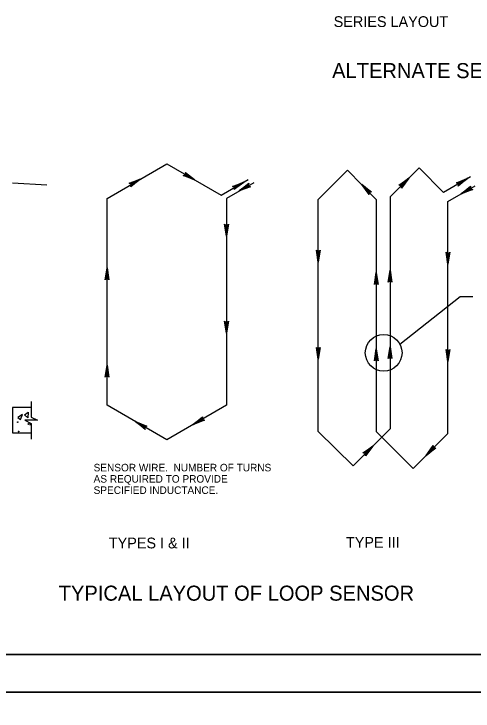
# Model space of a CAD drawing. Extents: x 2709 to 3899, y 22 to 1210.
# Drawn here: x 3073.4 to 3256.6, y 608.7 to 886.6 of the extents above; entities that cross this region are included whole.
import ezdxf

# ---------------------------------------------------------------- set-up
doc = ezdxf.new("R2010")
doc.units = 0
for name, color, linetype in [('1', 7, 'Continuous'), ('17', 7, 'Continuous'), ('2', 7, 'Continuous'), ('PLT-BNDY', 7, 'Continuous')]:
    doc.layers.add(name, color=color, linetype=linetype)

msp = doc.modelspace()

# ---------------------------------------------------------------- linework, layer by layer
at = {"layer": '1'}
for p, q in [((3534.86, 631.17), (2748.86, 631.17)), ((2748.86, 631.17), (3334.86, 631.17))]:
    msp.add_line(p, q, dxfattribs=at)
at = {"layer": '2'}
msp.add_line((3072.77, 819.25), (3086.52, 818.5), dxfattribs=at)
for points in [[(3158.17, 813.05), (3158.17, 730.55), (3134.42, 716.8), (3110.55, 730.55), (3110.55, 813.05), (3134.42, 826.8), (3156.05, 814.3)], [(3141.8, 823.17), (3141.8, 822.8), (3145.42, 820.42), (3141.8, 823.17), (3141.67, 823.42), (3145.42, 820.42), (3141.55, 822.42), (3141.3, 822.17), (3145.42, 820.42), (3140.92, 822.17), (3141.3, 822.17)], [(3255.55, 821.67), (3244.8, 815.42), (3235.05, 825.17), (3223.42, 813.67), (3223.42, 721.17), (3208.67, 706.42), (3194.8, 720.17), (3194.8, 812.67), (3206.42, 824.3), (3217.92, 812.67), (3217.92, 720.17), (3232.67, 705.42), (3246.55, 719.3), (3246.55, 811.8), (3257.42, 818.05)], [(3119.67, 818.92), (3119.92, 818.8), (3123.8, 820.67), (3119.67, 818.92), (3119.3, 819.05), (3123.8, 820.67), (3120.17, 818.3), (3120.17, 818.05), (3123.8, 820.67), (3120.05, 817.67), (3120.17, 818.05)], [(3156.05, 814.3), (3166.8, 820.55)], [(3227.3, 818.3), (3227.55, 818.17), (3230.92, 821.05), (3227.3, 818.3), (3226.92, 818.3), (3230.92, 821.05), (3227.92, 817.8), (3228.05, 817.55), (3230.92, 821.05), (3228.05, 817.17), (3228.05, 817.55)], [(3250.17, 819.17), (3250.55, 819.05), (3254.42, 821.05), (3250.17, 819.17), (3249.92, 819.3), (3254.42, 821.05), (3250.8, 818.67), (3250.8, 818.3), (3254.42, 821.05), (3250.67, 817.92), (3250.8, 818.3)], [(3169.05, 819.3), (3158.17, 813.05)], [(3160.92, 817.8), (3161.17, 817.55), (3165.05, 819.55), (3160.92, 817.8), (3160.55, 817.8), (3165.05, 819.55), (3161.42, 817.17), (3161.42, 816.8), (3165.05, 819.55), (3161.3, 816.55), (3161.42, 816.8)], [(3167.42, 817.8), (3167.17, 817.92), (3163.3, 816.05), (3167.42, 817.8), (3167.8, 817.67), (3163.3, 816.05), (3166.92, 818.42), (3166.92, 818.67), (3163.3, 816.05), (3167.05, 819.05), (3166.92, 818.67)], [(3214.92, 814.92), (3215.05, 815.17), (3212.17, 818.55), (3214.92, 814.92), (3215.05, 814.55), (3212.17, 818.55), (3215.42, 815.55), (3215.8, 815.67), (3212.17, 818.55), (3216.05, 815.67), (3215.8, 815.67)], [(3256.05, 816.55), (3255.8, 816.8), (3251.8, 814.8), (3256.05, 816.55), (3256.42, 816.55), (3251.8, 814.8), (3255.55, 817.17), (3255.55, 817.55), (3251.8, 814.8), (3255.55, 817.92), (3255.55, 817.55)], [(3158.8, 802.55), (3158.42, 802.42), (3158.17, 798.05), (3158.8, 802.55), (3158.92, 802.8), (3158.17, 798.05), (3157.92, 802.42), (3157.67, 802.55), (3158.17, 798.05), (3157.42, 802.8), (3157.67, 802.55)], [(3195.42, 792.17), (3195.05, 792.05), (3194.8, 787.67), (3195.42, 792.17), (3195.55, 792.42), (3194.8, 787.67), (3194.55, 792.05), (3194.3, 792.17), (3194.8, 787.67), (3194.05, 792.42), (3194.3, 792.17)], [(3247.17, 791.3), (3246.8, 791.05), (3246.55, 786.8), (3247.17, 791.3), (3247.3, 791.55), (3246.55, 786.8), (3246.3, 791.05), (3246.05, 791.3), (3246.55, 786.8), (3245.8, 791.55), (3246.05, 791.3)], [(3109.92, 780.8), (3110.3, 780.92), (3110.55, 785.3), (3109.92, 780.8), (3109.8, 780.55), (3110.55, 785.3), (3110.8, 780.92), (3111.05, 780.8), (3110.55, 785.3), (3111.3, 780.55), (3111.05, 780.8)], [(3222.92, 779.92), (3223.17, 780.05), (3223.42, 784.42), (3222.92, 779.92), (3222.67, 779.67), (3223.42, 784.42), (3223.67, 780.05), (3224.05, 779.92), (3223.42, 784.42), (3224.17, 779.67), (3224.05, 779.92)], [(3217.3, 778.92), (3217.67, 779.17), (3217.92, 783.55), (3217.3, 778.92), (3217.17, 778.67), (3217.92, 783.55), (3218.17, 779.17), (3218.42, 778.92), (3217.92, 783.55), (3218.67, 778.67), (3218.42, 778.92)], [(3256.42, 773.8), (3251.42, 773.8), (3227.3, 754.8)], [(3158.8, 763.8), (3158.42, 763.67), (3158.17, 759.3), (3158.8, 763.8), (3158.92, 764.05), (3158.17, 759.3), (3157.92, 763.67), (3157.67, 763.8), (3158.17, 759.3), (3157.42, 764.05), (3157.67, 763.8)], [(3195.42, 753.42), (3195.05, 753.3), (3194.8, 748.92), (3195.42, 753.42), (3195.55, 753.67), (3194.8, 748.92), (3194.55, 753.3), (3194.3, 753.42), (3194.8, 748.92), (3194.05, 753.67), (3194.3, 753.42)], [(3222.92, 749.42), (3223.17, 749.55), (3223.42, 753.92), (3222.92, 749.42), (3222.67, 749.17), (3223.42, 753.92), (3223.67, 749.67), (3224.05, 749.42), (3223.42, 753.92), (3224.17, 749.17), (3224.05, 749.42)], [(3217.3, 748.55), (3217.67, 748.67), (3217.92, 753.05), (3217.3, 748.55), (3217.17, 748.3), (3217.92, 753.05), (3218.17, 748.67), (3218.42, 748.55), (3217.92, 753.05), (3218.67, 748.3), (3218.42, 748.55)], [(3247.17, 752.55), (3246.8, 752.42), (3246.55, 748.05), (3247.17, 752.55), (3247.3, 752.8), (3246.55, 748.05), (3246.3, 752.3), (3246.05, 752.55), (3246.55, 748.05), (3245.8, 752.8), (3246.05, 752.55)], [(3109.92, 742.05), (3110.3, 742.17), (3110.55, 746.55), (3109.92, 742.05), (3109.8, 741.8), (3110.55, 746.55), (3110.8, 742.17), (3111.05, 742.05), (3110.55, 746.55), (3111.3, 741.8), (3111.05, 742.05)], [(3080.27, 732.12), (3080.27, 725.87), (3082.77, 724.62), (3077.77, 724.62), (3080.27, 723.37), (3080.27, 717.12)], [(3080.27, 729.62), (3080.27, 729.62), (3072.77, 729.62), (3072.77, 719.62), (3080.27, 719.62)], [(3149.17, 724.67), (3148.8, 724.92), (3144.92, 722.92), (3149.17, 724.67), (3149.42, 724.67), (3144.92, 722.92), (3148.55, 725.3), (3148.55, 725.67), (3144.92, 722.92), (3148.67, 725.92), (3148.55, 725.67)], [(3080.27, 723.12), (3079.77, 722.75)], [(3079.77, 722.75), (3080.27, 722.87)], [(3125.55, 721.3), (3125.55, 721.55), (3121.92, 724.05), (3125.55, 721.3), (3125.67, 720.92), (3121.92, 724.05), (3125.8, 722.05), (3126.05, 722.17), (3121.92, 724.05), (3126.42, 722.3), (3126.05, 722.17)], [(3212.92, 711.55), (3213.3, 711.42), (3216.55, 714.3), (3212.92, 711.55), (3212.55, 711.55), (3216.55, 714.3), (3213.55, 711.17), (3213.67, 710.8), (3216.55, 714.3), (3213.67, 710.42), (3213.67, 710.8)], [(3241.42, 713.42), (3241.05, 713.55), (3237.8, 710.55), (3241.42, 713.42), (3241.67, 713.42), (3237.8, 710.55), (3240.8, 713.8), (3240.67, 714.17), (3237.8, 710.55), (3240.67, 714.55), (3240.67, 714.17)]]:
    msp.add_lwpolyline(points, dxfattribs=at)
for points in [[(3076.77, 726.87), (3074.89, 725.75), (3076.02, 724.87)], [(3077.64, 726.75), (3079.02, 727.87), (3078.89, 725.5)]]:
    msp.add_lwpolyline(points, close=True, dxfattribs=at)
for centre, radius in [((3220.89, 751.49), 7.32), ((3074.89, 723.83), 0.138), ((3079.17, 723.11), 0.138), ((3075.24, 720.09), 0.138)]:
    msp.add_circle(centre, radius, dxfattribs=at)
at = {"layer": 'PLT-BNDY'}
for points in [[(2708.86, 1210.17), (3549.86, 1210.17), (3549.86, 616.17), (2708.86, 616.17)], [(2708.86, 616.17), (3549.86, 616.17), (3549.86, 22.17), (2708.86, 22.17)]]:
    msp.add_lwpolyline(points, close=True, dxfattribs=at)

# ---------------------------------------------------------------- texts
at = {"layer": '17'}
msp.add_text('SERIES LAYOUT', height=4.3, dxfattribs=at).set_placement((3200.94, 881.37))
at = {"layer": '2'}
for s, height, p in [('ALTERNATE SENSOR INSTALLATION - LOOP DETECTOR', 6, (3200.31, 860.98)), ('SENSOR WIRE.  NUMBER OF TURNS', 3, (3105.17, 704.23)), ('AS REQUIRED TO PROVIDE', 3, (3105.17, 699.73)), ('SPECIFIED INDUCTANCE.', 3, (3105.17, 695.23)), ('TYPES I & II', 4.3, (3111.23, 673.52)), ('TYPE III', 4.3, (3205.83, 673.77)), ('TYPICAL LAYOUT OF LOOP SENSOR', 6, (3091.23, 652.67))]:
    msp.add_text(s, height=height, dxfattribs=at).set_placement(p)

doc.saveas('drawing.dxf')
